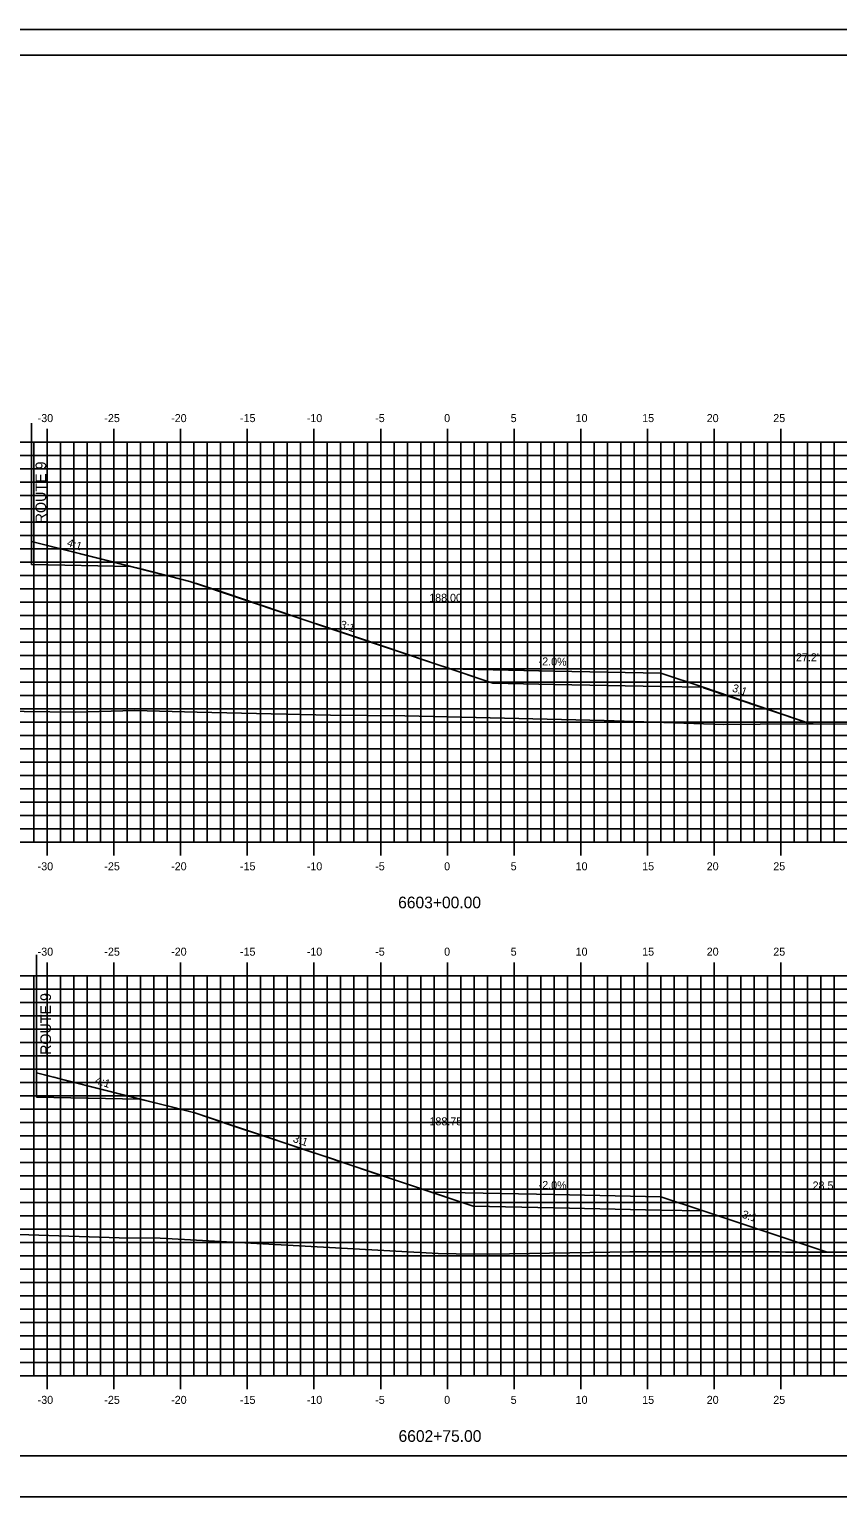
# Model space of a CAD drawing. Extents: x 1724405 to 1724577, y 459560 to 459670.
# Drawn here: x 1724456.6 to 1724517.3, y 459559.6 to 459669.6 of the extents above; entities that cross this region are included whole.
import ezdxf

# ---------------------------------------------------------------- set-up
doc = ezdxf.new("R2010")
doc.units = 0
for name, color, linetype in [('ANNOTATION', 7, 'Continuous'), ('BORDER', 7, 'Continuous'), ('D_Roadway_Centerline', 7, 'Continuous'), ('D_Roadway_Centerline_Text', 7, 'Continuous'), ('D_Roadway_Drive_Gravel', 7, 'Continuous'), ('D_Roadway_Edge_Shoulder', 7, 'Continuous'), ('D_Roadway_SlopeLines', 7, 'Continuous'), ('D_Roadway_SubGrade', 7, 'Continuous'), ('D_Text_Standard', 7, 'Continuous'), ('H_V ANNOTATION', 7, 'Continuous'), ('MAJOR', 7, 'Continuous'), ('MINOR', 7, 'Continuous'), ('PLOT BOUNDARY', 7, 'Continuous'), ('S_Roadway_Centerline', 7, 'Continuous')]:
    doc.layers.add(name, color=color, linetype=linetype)

msp = doc.modelspace()

# ---------------------------------------------------------------- linework, layer by layer
for points in [[(1724487.99, 459621.61), (1724495.99, 459621.45), (1724503.99, 459621.29), (1724507.18, 459620.23), (1724507.2, 459620.18), (1724511.79, 459618.65), (1724515.21, 459617.48), (1724515.42, 459617.48)], [(1724487.99, 459582.36), (1724495.99, 459582.2), (1724503.99, 459582.04), (1724507.18, 459580.98), (1724516.48, 459577.88), (1724516.51, 459577.87), (1724516.55, 459577.85)]]:
    msp.add_lwpolyline(points)
at = {"layer": 'BORDER'}
msp.add_lwpolyline([(1724412.99, 459562.61), (1724572.99, 459562.61), (1724572.99, 459667.61), (1724412.99, 459667.61)], close=True, dxfattribs=at)
at = {"layer": 'D_Roadway_Centerline'}
for points in [[(1724456.81, 459631.16), (1724462.71, 459629.68), (1724464.17, 459629.31), (1724464.19, 459629.31), (1724464.28, 459629.28), (1724465, 459629.1), (1724468.69, 459628.17), (1724469.14, 459628.02), (1724469.18, 459628.01), (1724471.9, 459627.1), (1724472.33, 459626.95), (1724475.57, 459625.86), (1724476.59, 459625.52), (1724479.6, 459624.51), (1724480.51, 459624.2), (1724481.99, 459623.71), (1724484.73, 459622.79), (1724487.31, 459621.92), (1724488, 459621.69), (1724488.42, 459621.55), (1724491.41, 459620.54)], [(1724457.17, 459591.32), (1724458.25, 459591.05), (1724458.47, 459590.99), (1724459.6, 459590.7), (1724464.16, 459589.56), (1724464.67, 459589.43), (1724464.94, 459589.36), (1724467.31, 459588.77), (1724469.05, 459588.33), (1724471.1, 459587.64), (1724471.39, 459587.54), (1724475.01, 459586.33), (1724475.53, 459586.15), (1724477.52, 459585.49), (1724479.22, 459584.92), (1724482.72, 459583.74), (1724483.28, 459583.55), (1724483.95, 459583.33), (1724487.82, 459582.03), (1724489.93, 459581.32)]]:
    msp.add_lwpolyline(points, dxfattribs=at)
at = {"layer": 'D_Roadway_Drive_Gravel'}
for points in [[(1724488.24, 459621.61), (1724495.99, 459621.45), (1724503.99, 459621.29), (1724507.18, 459620.23), (1724503.99, 459620.29), (1724495.99, 459620.45), (1724491.41, 459620.54)], [(1724487.99, 459582.36), (1724495.99, 459582.2), (1724503.99, 459582.04), (1724507.18, 459580.98), (1724503.99, 459581.04), (1724495.99, 459581.2), (1724489.93, 459581.32)], [(1724487.99, 459581.98), (1724487.99, 459581.98)]]:
    msp.add_lwpolyline(points, dxfattribs=at)
at = {"layer": 'D_Roadway_Edge_Shoulder'}
for p, q in [((1724456.81, 459631.16), (1724456.81, 459630.91)), ((1724456.81, 459631.16), (1724456.81, 459630.91)), ((1724457.17, 459591.32), (1724457.17, 459591.07)), ((1724457.17, 459591.32), (1724457.17, 459591.07))]:
    msp.add_line(p, q, dxfattribs=at)
at = {"layer": 'D_Roadway_SlopeLines'}
for points in [[(1724456.81, 459631.16), (1724468.69, 459628.17), (1724491.41, 459620.54)], [(1724456.81, 459631.16), (1724468.69, 459628.17), (1724491.41, 459620.54)], [(1724456.81, 459631.16), (1724468.69, 459628.17), (1724491.41, 459620.54)], [(1724456.81, 459631.16), (1724468.69, 459628.17), (1724491.41, 459620.54)], [(1724456.81, 459631.16), (1724468.69, 459628.17), (1724491.41, 459620.54)], [(1724456.81, 459631.16), (1724468.69, 459628.17), (1724491.41, 459620.54)], [(1724456.81, 459631.16), (1724468.69, 459628.17), (1724491.41, 459620.54)], [(1724503.99, 459621.29), (1724507.18, 459620.23), (1724515.21, 459617.48)], [(1724457.17, 459591.32), (1724469.05, 459588.33), (1724489.93, 459581.32)], [(1724457.17, 459591.32), (1724469.05, 459588.33), (1724489.93, 459581.32)], [(1724457.17, 459591.32), (1724469.05, 459588.33), (1724489.93, 459581.32)], [(1724457.17, 459591.32), (1724469.05, 459588.33), (1724489.93, 459581.32)], [(1724457.17, 459591.32), (1724469.05, 459588.33), (1724489.93, 459581.32)], [(1724457.17, 459591.32), (1724469.05, 459588.33), (1724489.93, 459581.32)], [(1724457.17, 459591.32), (1724469.05, 459588.33), (1724489.93, 459581.32)], [(1724503.99, 459582.04), (1724507.18, 459580.98), (1724516.48, 459577.88)]]:
    msp.add_lwpolyline(points, dxfattribs=at)
at = {"layer": 'D_Roadway_SubGrade'}
for p, q in [((1724456.81, 459640.02), (1724456.81, 459629.43)), ((1724457.17, 459600.18), (1724457.17, 459589.51)), ((1724487.99, 459582.36), (1724486.76, 459582.39))]:
    msp.add_line(p, q, dxfattribs=at)
for points in [[(1724456.81, 459630.91), (1724456.81, 459631.16), (1724464.28, 459629.28), (1724456.81, 459629.43)], [(1724456.81, 459630.91), (1724456.81, 459631.16), (1724464.28, 459629.28), (1724456.81, 459629.43)], [(1724457.17, 459591.07), (1724457.17, 459591.32), (1724464.94, 459589.36), (1724457.17, 459589.51)], [(1724457.17, 459591.07), (1724457.17, 459591.32), (1724464.94, 459589.36), (1724457.17, 459589.51)]]:
    msp.add_lwpolyline(points, dxfattribs=at)
at = {"layer": 'MAJOR'}
for p, q in [((1724457.99, 459639.61), (1724457.99, 459638.61)), ((1724462.99, 459639.61), (1724462.99, 459638.61)), ((1724467.99, 459639.61), (1724467.99, 459638.61)), ((1724472.99, 459639.61), (1724472.99, 459638.61)), ((1724477.99, 459639.61), (1724477.99, 459638.61)), ((1724482.99, 459639.61), (1724482.99, 459638.61)), ((1724487.99, 459639.61), (1724487.99, 459638.61)), ((1724492.99, 459639.61), (1724492.99, 459638.61)), ((1724497.99, 459639.61), (1724497.99, 459638.61)), ((1724502.99, 459639.61), (1724502.99, 459638.61)), ((1724507.99, 459639.61), (1724507.99, 459638.61)), ((1724512.99, 459639.61), (1724512.99, 459638.61)), ((1724417.99, 459638.61), (1724557.99, 459638.61)), ((1724417.99, 459638.61), (1724557.99, 459638.61)), ((1724457.99, 459608.61), (1724457.99, 459638.61)), ((1724462.99, 459608.61), (1724462.99, 459638.61)), ((1724467.99, 459608.61), (1724467.99, 459638.61)), ((1724472.99, 459608.61), (1724472.99, 459638.61)), ((1724477.99, 459608.61), (1724477.99, 459638.61)), ((1724482.99, 459608.61), (1724482.99, 459638.61)), ((1724487.99, 459608.61), (1724487.99, 459638.61)), ((1724492.99, 459608.61), (1724492.99, 459638.61)), ((1724497.99, 459608.61), (1724497.99, 459638.61)), ((1724502.99, 459608.61), (1724502.99, 459638.61)), ((1724507.99, 459608.61), (1724507.99, 459638.61)), ((1724512.99, 459608.61), (1724512.99, 459638.61)), ((1724417.99, 459633.61), (1724557.99, 459633.61)), ((1724417.99, 459628.61), (1724557.99, 459628.61)), ((1724417.99, 459623.61), (1724557.99, 459623.61)), ((1724417.99, 459618.61), (1724557.99, 459618.61)), ((1724417.99, 459613.61), (1724557.99, 459613.61)), ((1724417.99, 459608.61), (1724557.99, 459608.61)), ((1724417.99, 459608.61), (1724557.99, 459608.61)), ((1724457.99, 459607.61), (1724457.99, 459608.61)), ((1724462.99, 459607.61), (1724462.99, 459608.61)), ((1724467.99, 459607.61), (1724467.99, 459608.61)), ((1724472.99, 459607.61), (1724472.99, 459608.61)), ((1724477.99, 459607.61), (1724477.99, 459608.61)), ((1724482.99, 459607.61), (1724482.99, 459608.61)), ((1724487.99, 459607.61), (1724487.99, 459608.61)), ((1724492.99, 459607.61), (1724492.99, 459608.61)), ((1724497.99, 459607.61), (1724497.99, 459608.61)), ((1724502.99, 459607.61), (1724502.99, 459608.61)), ((1724507.99, 459607.61), (1724507.99, 459608.61)), ((1724512.99, 459607.61), (1724512.99, 459608.61)), ((1724457.99, 459599.61), (1724457.99, 459598.61)), ((1724462.99, 459599.61), (1724462.99, 459598.61)), ((1724467.99, 459599.61), (1724467.99, 459598.61)), ((1724472.99, 459599.61), (1724472.99, 459598.61)), ((1724477.99, 459599.61), (1724477.99, 459598.61)), ((1724482.99, 459599.61), (1724482.99, 459598.61)), ((1724487.99, 459599.61), (1724487.99, 459598.61)), ((1724492.99, 459599.61), (1724492.99, 459598.61)), ((1724497.99, 459599.61), (1724497.99, 459598.61)), ((1724502.99, 459599.61), (1724502.99, 459598.61)), ((1724507.99, 459599.61), (1724507.99, 459598.61)), ((1724512.99, 459599.61), (1724512.99, 459598.61)), ((1724417.99, 459598.61), (1724557.99, 459598.61)), ((1724417.99, 459598.61), (1724557.99, 459598.61)), ((1724457.99, 459568.61), (1724457.99, 459598.61)), ((1724462.99, 459568.61), (1724462.99, 459598.61)), ((1724467.99, 459568.61), (1724467.99, 459598.61)), ((1724472.99, 459568.61), (1724472.99, 459598.61)), ((1724477.99, 459568.61), (1724477.99, 459598.61)), ((1724482.99, 459568.61), (1724482.99, 459598.61)), ((1724487.99, 459568.61), (1724487.99, 459598.61)), ((1724492.99, 459568.61), (1724492.99, 459598.61)), ((1724497.99, 459568.61), (1724497.99, 459598.61)), ((1724502.99, 459568.61), (1724502.99, 459598.61)), ((1724507.99, 459568.61), (1724507.99, 459598.61)), ((1724512.99, 459568.61), (1724512.99, 459598.61)), ((1724417.99, 459593.61), (1724557.99, 459593.61)), ((1724417.99, 459588.61), (1724557.99, 459588.61)), ((1724417.99, 459583.61), (1724557.99, 459583.61)), ((1724417.99, 459578.61), (1724557.99, 459578.61)), ((1724417.99, 459573.61), (1724557.99, 459573.61)), ((1724417.99, 459568.61), (1724557.99, 459568.61)), ((1724417.99, 459568.61), (1724557.99, 459568.61)), ((1724457.99, 459567.61), (1724457.99, 459568.61)), ((1724462.99, 459567.61), (1724462.99, 459568.61)), ((1724467.99, 459567.61), (1724467.99, 459568.61)), ((1724472.99, 459567.61), (1724472.99, 459568.61)), ((1724477.99, 459567.61), (1724477.99, 459568.61)), ((1724482.99, 459567.61), (1724482.99, 459568.61)), ((1724487.99, 459567.61), (1724487.99, 459568.61)), ((1724492.99, 459567.61), (1724492.99, 459568.61)), ((1724497.99, 459567.61), (1724497.99, 459568.61)), ((1724502.99, 459567.61), (1724502.99, 459568.61)), ((1724507.99, 459567.61), (1724507.99, 459568.61)), ((1724512.99, 459567.61), (1724512.99, 459568.61))]:
    msp.add_line(p, q, dxfattribs=at)
at = {"layer": 'MINOR'}
for p, q in [((1724456.99, 459608.61), (1724456.99, 459638.61)), ((1724458.99, 459608.61), (1724458.99, 459638.61)), ((1724459.99, 459608.61), (1724459.99, 459638.61)), ((1724460.99, 459608.61), (1724460.99, 459638.61)), ((1724461.99, 459608.61), (1724461.99, 459638.61)), ((1724463.99, 459608.61), (1724463.99, 459638.61)), ((1724464.99, 459608.61), (1724464.99, 459638.61)), ((1724465.99, 459608.61), (1724465.99, 459638.61)), ((1724466.99, 459608.61), (1724466.99, 459638.61)), ((1724468.99, 459608.61), (1724468.99, 459638.61)), ((1724469.99, 459608.61), (1724469.99, 459638.61)), ((1724470.99, 459608.61), (1724470.99, 459638.61)), ((1724471.99, 459608.61), (1724471.99, 459638.61)), ((1724473.99, 459608.61), (1724473.99, 459638.61)), ((1724474.99, 459608.61), (1724474.99, 459638.61)), ((1724475.99, 459608.61), (1724475.99, 459638.61)), ((1724476.99, 459608.61), (1724476.99, 459638.61)), ((1724478.99, 459608.61), (1724478.99, 459638.61)), ((1724479.99, 459608.61), (1724479.99, 459638.61)), ((1724480.99, 459608.61), (1724480.99, 459638.61)), ((1724481.99, 459608.61), (1724481.99, 459638.61)), ((1724483.99, 459608.61), (1724483.99, 459638.61)), ((1724484.99, 459608.61), (1724484.99, 459638.61)), ((1724485.99, 459608.61), (1724485.99, 459638.61)), ((1724486.99, 459608.61), (1724486.99, 459638.61)), ((1724488.99, 459608.61), (1724488.99, 459638.61)), ((1724489.99, 459608.61), (1724489.99, 459638.61)), ((1724490.99, 459608.61), (1724490.99, 459638.61)), ((1724491.99, 459608.61), (1724491.99, 459638.61)), ((1724493.99, 459608.61), (1724493.99, 459638.61)), ((1724494.99, 459608.61), (1724494.99, 459638.61)), ((1724495.99, 459608.61), (1724495.99, 459638.61)), ((1724496.99, 459608.61), (1724496.99, 459638.61)), ((1724498.99, 459608.61), (1724498.99, 459638.61)), ((1724499.99, 459608.61), (1724499.99, 459638.61)), ((1724500.99, 459608.61), (1724500.99, 459638.61)), ((1724501.99, 459608.61), (1724501.99, 459638.61)), ((1724503.99, 459608.61), (1724503.99, 459638.61)), ((1724504.99, 459608.61), (1724504.99, 459638.61)), ((1724505.99, 459608.61), (1724505.99, 459638.61)), ((1724506.99, 459608.61), (1724506.99, 459638.61)), ((1724508.99, 459608.61), (1724508.99, 459638.61)), ((1724509.99, 459608.61), (1724509.99, 459638.61)), ((1724510.99, 459608.61), (1724510.99, 459638.61)), ((1724511.99, 459608.61), (1724511.99, 459638.61)), ((1724513.99, 459608.61), (1724513.99, 459638.61)), ((1724514.99, 459608.61), (1724514.99, 459638.61)), ((1724515.99, 459608.61), (1724515.99, 459638.61)), ((1724516.99, 459608.61), (1724516.99, 459638.61)), ((1724417.99, 459637.61), (1724557.99, 459637.61)), ((1724417.99, 459636.61), (1724557.99, 459636.61)), ((1724417.99, 459635.61), (1724557.99, 459635.61)), ((1724417.99, 459634.61), (1724557.99, 459634.61)), ((1724417.99, 459632.61), (1724557.99, 459632.61)), ((1724417.99, 459631.61), (1724557.99, 459631.61)), ((1724417.99, 459630.61), (1724557.99, 459630.61)), ((1724417.99, 459629.61), (1724557.99, 459629.61)), ((1724417.99, 459627.61), (1724557.99, 459627.61)), ((1724417.99, 459626.61), (1724557.99, 459626.61)), ((1724417.99, 459625.61), (1724557.99, 459625.61)), ((1724417.99, 459624.61), (1724557.99, 459624.61)), ((1724417.99, 459622.61), (1724557.99, 459622.61)), ((1724417.99, 459621.61), (1724557.99, 459621.61)), ((1724417.99, 459620.61), (1724557.99, 459620.61)), ((1724417.99, 459619.61), (1724557.99, 459619.61)), ((1724417.99, 459617.61), (1724557.99, 459617.61)), ((1724417.99, 459616.61), (1724557.99, 459616.61)), ((1724417.99, 459615.61), (1724557.99, 459615.61)), ((1724417.99, 459614.61), (1724557.99, 459614.61)), ((1724417.99, 459612.61), (1724557.99, 459612.61)), ((1724417.99, 459611.61), (1724557.99, 459611.61)), ((1724417.99, 459610.61), (1724557.99, 459610.61)), ((1724417.99, 459609.61), (1724557.99, 459609.61)), ((1724417.99, 459597.61), (1724557.99, 459597.61)), ((1724456.99, 459568.61), (1724456.99, 459598.61)), ((1724458.99, 459568.61), (1724458.99, 459598.61)), ((1724459.99, 459568.61), (1724459.99, 459598.61)), ((1724460.99, 459568.61), (1724460.99, 459598.61)), ((1724461.99, 459568.61), (1724461.99, 459598.61)), ((1724463.99, 459568.61), (1724463.99, 459598.61)), ((1724464.99, 459568.61), (1724464.99, 459598.61)), ((1724465.99, 459568.61), (1724465.99, 459598.61)), ((1724466.99, 459568.61), (1724466.99, 459598.61)), ((1724468.99, 459568.61), (1724468.99, 459598.61)), ((1724469.99, 459568.61), (1724469.99, 459598.61)), ((1724470.99, 459568.61), (1724470.99, 459598.61)), ((1724471.99, 459568.61), (1724471.99, 459598.61)), ((1724473.99, 459568.61), (1724473.99, 459598.61)), ((1724474.99, 459568.61), (1724474.99, 459598.61)), ((1724475.99, 459568.61), (1724475.99, 459598.61)), ((1724476.99, 459568.61), (1724476.99, 459598.61)), ((1724478.99, 459568.61), (1724478.99, 459598.61)), ((1724479.99, 459568.61), (1724479.99, 459598.61)), ((1724480.99, 459568.61), (1724480.99, 459598.61)), ((1724481.99, 459568.61), (1724481.99, 459598.61)), ((1724483.99, 459568.61), (1724483.99, 459598.61)), ((1724484.99, 459568.61), (1724484.99, 459598.61)), ((1724485.99, 459568.61), (1724485.99, 459598.61)), ((1724486.99, 459568.61), (1724486.99, 459598.61)), ((1724488.99, 459568.61), (1724488.99, 459598.61)), ((1724489.99, 459568.61), (1724489.99, 459598.61)), ((1724490.99, 459568.61), (1724490.99, 459598.61)), ((1724491.99, 459568.61), (1724491.99, 459598.61)), ((1724493.99, 459568.61), (1724493.99, 459598.61)), ((1724494.99, 459568.61), (1724494.99, 459598.61)), ((1724495.99, 459568.61), (1724495.99, 459598.61)), ((1724496.99, 459568.61), (1724496.99, 459598.61)), ((1724498.99, 459568.61), (1724498.99, 459598.61)), ((1724499.99, 459568.61), (1724499.99, 459598.61)), ((1724500.99, 459568.61), (1724500.99, 459598.61)), ((1724501.99, 459568.61), (1724501.99, 459598.61)), ((1724503.99, 459568.61), (1724503.99, 459598.61)), ((1724504.99, 459568.61), (1724504.99, 459598.61)), ((1724505.99, 459568.61), (1724505.99, 459598.61)), ((1724506.99, 459568.61), (1724506.99, 459598.61)), ((1724508.99, 459568.61), (1724508.99, 459598.61)), ((1724509.99, 459568.61), (1724509.99, 459598.61)), ((1724510.99, 459568.61), (1724510.99, 459598.61)), ((1724511.99, 459568.61), (1724511.99, 459598.61)), ((1724513.99, 459568.61), (1724513.99, 459598.61)), ((1724514.99, 459568.61), (1724514.99, 459598.61)), ((1724515.99, 459568.61), (1724515.99, 459598.61)), ((1724516.99, 459568.61), (1724516.99, 459598.61)), ((1724417.99, 459596.61), (1724557.99, 459596.61)), ((1724417.99, 459595.61), (1724557.99, 459595.61)), ((1724417.99, 459594.61), (1724557.99, 459594.61)), ((1724417.99, 459592.61), (1724557.99, 459592.61)), ((1724417.99, 459591.61), (1724557.99, 459591.61)), ((1724417.99, 459590.61), (1724557.99, 459590.61)), ((1724417.99, 459589.61), (1724557.99, 459589.61)), ((1724417.99, 459587.61), (1724557.99, 459587.61)), ((1724417.99, 459586.61), (1724557.99, 459586.61)), ((1724417.99, 459585.61), (1724557.99, 459585.61)), ((1724417.99, 459584.61), (1724557.99, 459584.61)), ((1724417.99, 459582.61), (1724557.99, 459582.61)), ((1724417.99, 459581.61), (1724557.99, 459581.61)), ((1724417.99, 459580.61), (1724557.99, 459580.61)), ((1724417.99, 459579.61), (1724557.99, 459579.61)), ((1724417.99, 459577.61), (1724557.99, 459577.61)), ((1724417.99, 459576.61), (1724557.99, 459576.61)), ((1724417.99, 459575.61), (1724557.99, 459575.61)), ((1724417.99, 459574.61), (1724557.99, 459574.61)), ((1724417.99, 459572.61), (1724557.99, 459572.61)), ((1724417.99, 459571.61), (1724557.99, 459571.61)), ((1724417.99, 459570.61), (1724557.99, 459570.61)), ((1724417.99, 459569.61), (1724557.99, 459569.61))]:
    msp.add_line(p, q, dxfattribs=at)
at = {"layer": 'PLOT BOUNDARY'}
msp.add_lwpolyline([(1724404.89, 459559.55), (1724574.89, 459559.55), (1724574.89, 459669.55), (1724404.89, 459669.55)], close=True, dxfattribs=at)
at = {"layer": 'S_Roadway_Centerline'}
for points in [[(1724417.99, 459619.85), (1724418.89, 459619.83), (1724425.54, 459619.37), (1724434.97, 459618.78), (1724446.53, 459618.53), (1724460.12, 459618.37), (1724464.54, 459618.49), (1724469.23, 459618.37), (1724479.23, 459618.15), (1724484.8, 459618.1), (1724499.75, 459617.73), (1724508.71, 459617.44), (1724514.19, 459617.49), (1724532.07, 459617.41), (1724536.47, 459617.24), (1724545.7, 459617.02), (1724556.18, 459616.87), (1724557.88, 459616.89), (1724557.99, 459616.9)], [(1724417.99, 459580.32), (1724432.57, 459579.8), (1724439.05, 459579.67), (1724449.05, 459579.44), (1724463.39, 459578.96), (1724466.45, 459578.94), (1724487.3, 459577.78), (1724488.65, 459577.75), (1724491.14, 459577.74), (1724501.67, 459577.9), (1724512.87, 459577.9), (1724513.35, 459577.88), (1724523.87, 459577.87), (1724535, 459577.5), (1724536.23, 459577.43), (1724537.43, 459577.4), (1724557.22, 459577.48), (1724557.99, 459577.46)]]:
    msp.add_lwpolyline(points, dxfattribs=at)

# ---------------------------------------------------------------- texts
at = {"layer": 'ANNOTATION'}
for s, height, rotation, p in [('ROUTE 9', 0.8, 90, (1724457.91, 459632.52)), ('4:1', 0.6, 341.5651, (1724459.42, 459630.83)), ('3:1', 0.6, 341.5651, (1724479.89, 459624.7)), ('-2.0%', 0.6, 358.8542, (1724494.83, 459621.88)), ('3:1', 0.6, 341.5696, (1724509.3, 459619.93)), ('ROUTE 9', 0.8, 90, (1724458.27, 459592.67)), ('4:1', 0.6, 341.5651, (1724461.54, 459590.54)), ('3:1', 0.6, 341.5651, (1724476.36, 459586.16)), ('-2.0%', 0.6, 358.8542, (1724494.83, 459582.63)), ('3:1', 0.6, 341.5651, (1724510.03, 459580.48))]:
    msp.add_text(s, height=height, rotation=rotation, dxfattribs=at).set_placement(p)
at = {"layer": 'D_Roadway_Centerline_Text'}
for s, p in [('188.00', (1724486.63, 459626.64)), ('188.75', (1724486.65, 459587.39))]:
    msp.add_text(s, height=0.6, dxfattribs=at).set_placement(p)
at = {"layer": 'D_Text_Standard'}
for s, p in [("27.2'", (1724514.13, 459622.18)), ("28.5'", (1724515.38, 459582.58))]:
    msp.add_text(s, height=0.6, dxfattribs=at).set_placement(p)
at = {"layer": 'H_V ANNOTATION'}
for s, height, p in [('-30', 0.6, (1724457.27, 459640.11)), ('-25', 0.6, (1724462.27, 459640.11)), ('-20', 0.6, (1724467.28, 459640.11)), ('-15', 0.6, (1724472.44, 459640.11)), ('-10', 0.6, (1724477.45, 459640.11)), ('-5', 0.6, (1724482.58, 459640.11)), ('0', 0.6, (1724487.75, 459640.11)), ('5', 0.6, (1724492.74, 459640.11)), ('10', 0.6, (1724497.61, 459640.11)), ('15', 0.6, (1724502.6, 459640.11)), ('20', 0.6, (1724507.44, 459640.11)), ('25', 0.6, (1724512.43, 459640.11)), ('-30', 0.6, (1724457.27, 459606.51)), ('-25', 0.6, (1724462.27, 459606.51)), ('-20', 0.6, (1724467.28, 459606.51)), ('-15', 0.6, (1724472.44, 459606.51)), ('-10', 0.6, (1724477.45, 459606.51)), ('-5', 0.6, (1724482.58, 459606.51)), ('0', 0.6, (1724487.75, 459606.51)), ('5', 0.6, (1724492.74, 459606.51)), ('10', 0.6, (1724497.61, 459606.51)), ('15', 0.6, (1724502.6, 459606.51)), ('20', 0.6, (1724507.44, 459606.51)), ('25', 0.6, (1724512.43, 459606.51)), ('6603+00.00', 0.875, (1724484.3, 459603.66)), ('-30', 0.6, (1724457.27, 459600.11)), ('-25', 0.6, (1724462.27, 459600.11)), ('-20', 0.6, (1724467.28, 459600.11)), ('-15', 0.6, (1724472.44, 459600.11)), ('-10', 0.6, (1724477.45, 459600.11)), ('-5', 0.6, (1724482.58, 459600.11)), ('0', 0.6, (1724487.75, 459600.11)), ('5', 0.6, (1724492.74, 459600.11)), ('10', 0.6, (1724497.61, 459600.11)), ('15', 0.6, (1724502.6, 459600.11)), ('20', 0.6, (1724507.44, 459600.11)), ('25', 0.6, (1724512.43, 459600.11)), ('-30', 0.6, (1724457.27, 459566.51)), ('-25', 0.6, (1724462.27, 459566.51)), ('-20', 0.6, (1724467.28, 459566.51)), ('-15', 0.6, (1724472.44, 459566.51)), ('-10', 0.6, (1724477.45, 459566.51)), ('-5', 0.6, (1724482.58, 459566.51)), ('0', 0.6, (1724487.75, 459566.51)), ('5', 0.6, (1724492.74, 459566.51)), ('10', 0.6, (1724497.61, 459566.51)), ('15', 0.6, (1724502.6, 459566.51)), ('20', 0.6, (1724507.44, 459566.51)), ('25', 0.6, (1724512.43, 459566.51)), ('6602+75.00', 0.875, (1724484.33, 459563.66))]:
    msp.add_text(s, height=height, dxfattribs=at).set_placement(p)

doc.saveas('drawing.dxf')
